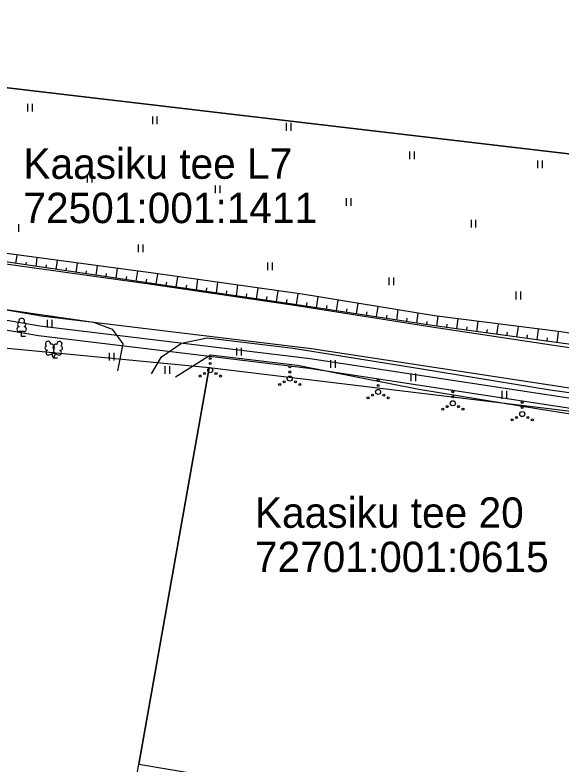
# Model space of a CAD drawing. Extents: x 532656 to 533339, y 6581345 to 6581629.
# Drawn here: x 532876.2 to 532930.1, y 6581458 to 6581531.9 of the extents above; entities that cross this region are included whole.
import ezdxf

# ---------------------------------------------------------------- set-up
doc = ezdxf.new("R2010")
doc.units = 0
for name, color, linetype in [('HALJASTUS', 7, 'Continuous'), ('KASUTUSALA', 7, 'Continuous'), ('PIIR', 7, 'Continuous'), ('PR_SIDE', 7, 'Continuous'), ('PUU', 7, 'Continuous'), ('RELJEEF', 7, 'Continuous'), ('TEE', 7, 'Continuous')]:
    doc.layers.add(name, color=color, linetype=linetype)

msp = doc.modelspace()

# ---------------------------------------------------------------- linework, layer by layer
at = {"layer": 'HALJASTUS'}
for p, q in [((532877.419, 6581523.158), (532877.419, 6581522.397)), ((532877.874, 6581523.158), (532877.874, 6581522.397)), ((532889.752, 6581521.902), (532889.752, 6581521.14)), ((532890.207, 6581521.902), (532890.207, 6581521.14)), ((532902.96, 6581521.263), (532902.96, 6581520.502)), ((532903.415, 6581521.263), (532903.415, 6581520.502)), ((532915.127, 6581518.44), (532915.127, 6581517.679)), ((532915.582, 6581518.44), (532915.582, 6581517.679)), ((532927.787, 6581517.553), (532927.787, 6581516.792)), ((532928.242, 6581517.553), (532928.242, 6581516.792)), ((532883.327, 6581516.137), (532883.327, 6581515.376)), ((532883.782, 6581516.137), (532883.782, 6581515.376)), ((532895.955, 6581515.103), (532895.955, 6581514.342)), ((532896.41, 6581515.103), (532896.41, 6581514.342)), ((532908.879, 6581513.846), (532908.879, 6581513.085)), ((532909.334, 6581513.846), (532909.334, 6581513.085)), ((532921.212, 6581511.703), (532921.212, 6581510.942)), ((532921.667, 6581511.703), (532921.667, 6581510.942)), ((532876.545, 6581511.26), (532876.545, 6581510.499)), ((532888.349, 6581509.265), (532888.349, 6581508.504)), ((532888.804, 6581509.265), (532888.804, 6581508.504)), ((532901.125, 6581507.491), (532901.125, 6581506.73)), ((532901.58, 6581507.491), (532901.58, 6581506.73)), ((532913.088, 6581506.013), (532913.088, 6581505.252)), ((532913.543, 6581506.013), (532913.543, 6581505.252)), ((532925.643, 6581504.609), (532925.643, 6581503.848)), ((532926.098, 6581504.609), (532926.098, 6581503.848)), ((532879.354, 6581501.818), (532879.354, 6581501.057)), ((532879.809, 6581501.818), (532879.809, 6581501.057)), ((532898.063, 6581499.063), (532898.063, 6581498.302)), ((532898.518, 6581499.063), (532898.518, 6581498.302)), ((532885.49, 6581498.566), (532885.49, 6581497.805)), ((532885.945, 6581498.566), (532885.945, 6581497.805)), ((532890.989, 6581497.249), (532890.989, 6581496.488)), ((532891.444, 6581497.249), (532891.444, 6581496.488)), ((532907.347, 6581497.838), (532907.347, 6581497.077)), ((532907.802, 6581497.838), (532907.802, 6581497.077)), ((532915.281, 6581496.529), (532915.281, 6581495.768)), ((532915.736, 6581496.529), (532915.736, 6581495.768)), ((532924.269, 6581494.798), (532924.269, 6581494.037)), ((532924.724, 6581494.798), (532924.724, 6581494.037))]:
    msp.add_line(p, q, dxfattribs=at)
msp.add_lwpolyline([(532892.02, 6581496.19), (532895.502, 6581498.379), (532904.073, 6581497.349), (532916.051, 6581494.964), (532928.105, 6581493.009), (532933.125, 6581492.214), (532933.659, 6581491.084)], dxfattribs=at)
for centre, radius in [((532895.468, 6581498.001), 0.1), ((532895.468, 6581497.501), 0.1), ((532903.319, 6581497.174), 0.1), ((532894.903, 6581496.526), 0.1), ((532895.468, 6581496.851), 0.25), ((532896.033, 6581496.526), 0.1), ((532903.319, 6581496.674), 0.1), ((532894.468, 6581496.276), 0.1), ((532896.468, 6581496.276), 0.1), ((532902.754, 6581495.699), 0.1), ((532903.319, 6581496.024), 0.25), ((532903.884, 6581495.699), 0.1), ((532912.039, 6581495.851), 0.1), ((532902.319, 6581495.449), 0.1), ((532904.319, 6581495.449), 0.1), ((532912.039, 6581495.351), 0.1), ((532911.474, 6581494.376), 0.1), ((532912.039, 6581494.701), 0.25), ((532912.604, 6581494.376), 0.1), ((532919.417, 6581494.729), 0.1), ((532919.417, 6581494.229), 0.1), ((532911.039, 6581494.126), 0.1), ((532913.039, 6581494.126), 0.1), ((532919.417, 6581493.579), 0.25), ((532926.265, 6581493.665), 0.1), ((532918.417, 6581493.004), 0.1), ((532918.852, 6581493.254), 0.1), ((532919.982, 6581493.254), 0.1), ((532920.417, 6581493.004), 0.1), ((532926.265, 6581493.165), 0.1), ((532925.265, 6581491.94), 0.1), ((532925.7, 6581492.19), 0.1), ((532926.265, 6581492.515), 0.25), ((532926.83, 6581492.19), 0.1), ((532927.265, 6581491.94), 0.1)]:
    msp.add_circle(centre, radius, dxfattribs=at)
at = {"layer": 'KASUTUSALA'}
for points in [[(532799.662, 6581479.424), (532838.202, 6581500.971), (532843.839, 6581502.808), (532856.06, 6581504.74), (532864.381, 6581504.708), (532878.783, 6581502.228), (532905.462, 6581499.009), (532934.405, 6581494.582), (532940.328, 6581500.726), (532975.953, 6581496.54), (532984.828, 6581495.375), (532991.779, 6581493.915), (533009.862, 6581492.726), (533014.729, 6581492.033), (533013.98, 6581493.304), (533015.896, 6581507.087)], [(533020.132, 6581489.243), (533009.655, 6581490.735), (532991.507, 6581491.928), (532984.492, 6581493.402), (532975.706, 6581494.555), (532941.079, 6581498.624), (532935.126, 6581492.449), (532905.191, 6581497.027), (532878.493, 6581500.248), (532864.206, 6581502.709), (532856.214, 6581502.739), (532844.308, 6581500.857), (532839.008, 6581499.129), (532800.682, 6581477.703)]]:
    msp.add_lwpolyline(points, dxfattribs=at)
at = {"layer": 'PIIR'}
for points in [[(532997.696, 6581510.35), (532853.02, 6581527.38), (532766.54, 6581476.67), (532710.965, 6581584.147)], [(532997.696, 6581484.842), (532936.25, 6581492.16), (532895.36, 6581497.07), (532858.61, 6581500.62), (532765.26, 6581446.64), (532740.99, 6581450.83), (532726.7, 6581453.3), (532853.02, 6581527.38), (532997.696, 6581510.35)]]:
    msp.add_lwpolyline(points, dxfattribs=at)
for points in [[(532858.61, 6581500.62), (532765.26, 6581446.64), (532882.56, 6581425.55), (532888.42, 6581457.95), (532895.36, 6581497.07)], [(532895.36, 6581497.07), (532888.42, 6581457.95), (532930.2, 6581450.9), (532936.25, 6581492.16)]]:
    msp.add_lwpolyline(points, close=True, dxfattribs=at)
at = {"layer": 'PR_SIDE'}
msp.add_lwpolyline([(532685.797, 6581460.812), (532752.673, 6581449.895), (532752.642, 6581449.863), (532756.241, 6581452.319), (532771.22, 6581460.368), (532800.172, 6581478.564), (532838.605, 6581500.05), (532844.074, 6581501.833), (532856.137, 6581503.74), (532864.294, 6581503.709), (532878.638, 6581501.239), (532905.327, 6581498.018), (532934.766, 6581493.516), (532940.704, 6581499.675), (532975.83, 6581495.548), (532984.66, 6581494.389), (532991.644, 6581492.922), (533009.759, 6581491.731), (533020.322, 6581490.227)], dxfattribs=at)
at = {"layer": 'PUU'}
for p, q in [((532877.086, 6581500.66), (532876.606, 6581500.66)), ((532876.845, 6581500.185), (532876.845, 6581500.66)), ((532877.226, 6581500.185), (532876.845, 6581500.185)), ((532879.562, 6581498.372), (532880.007, 6581498.547)), ((532880.002, 6581498.037), (532879.827, 6581498.477)), ((532880.002, 6581498.037), (532880.182, 6581498.477)), ((532880.382, 6581498.037), (532880.002, 6581498.037)), ((532880.007, 6581498.547), (532880.447, 6581498.367))]:
    msp.add_line(p, q, dxfattribs=at)
msp.add_lwpolyline([(532880.007, 6581499.042), (532879.987, 6581498.967), (532879.987, 6581498.947), (532879.997, 6581498.917), (532880.017, 6581498.882), (532880.022, 6581498.862), (532880.007, 6581498.827), (532879.982, 6581498.777), (532879.977, 6581498.752), (532879.982, 6581498.737), (532879.992, 6581498.707), (532880.027, 6581498.647), (532880.032, 6581498.627), (532880.027, 6581498.607), (532880.012, 6581498.572), (532880.007, 6581498.547)], dxfattribs=at)
for centre, radius, start, end in [((532876.845, 6581501.705), 0.277, 332.5799, 207.4201), ((532876.608, 6581500.898), 0.238, 90.0016, 269.3953), ((532876.675, 6581501.358), 0.233, 109.02174, 253.14154), ((532877.016, 6581501.358), 0.233, 286.85082, 70.98591), ((532877.083, 6581500.898), 0.238, 270.6047, 89.9984), ((532879.445, 6581499.451), 0.256, 111.50269, 232.51731), ((532879.445, 6581499.451), 0.256, 350.48556, 111.50017), ((532880.581, 6581499.442), 0.256, 67.6168, 188.63142), ((532880.581, 6581499.442), 0.256, 306.59966, 67.61428), ((532879.371, 6581499.039), 0.224, 111.43041, 274.49868), ((532879.476, 6581498.595), 0.237, 111.50143, 291.50036), ((532879.78, 6581499.2), 0.224, 308.50412, 111.57247), ((532880.006, 6581498.804), 0.237, 66.76552, 111.50149), ((532880.243, 6581499.196), 0.225, 67.7016, 230.51262), ((532880.537, 6581498.587), 0.237, 247.61661, 67.61554), ((532880.648, 6581499.029), 0.224, 264.6183, 67.68657)]:
    msp.add_arc(centre, radius, start, end, dxfattribs=at)
at = {"layer": 'RELJEEF'}
for p, q in [((532876.284, 6581507.389), (532876.406, 6581508.222)), ((532878.262, 6581507.097), (532878.389, 6581507.956)), ((532880.241, 6581506.806), (532880.371, 6581507.691)), ((532877.273, 6581507.243), (532877.314, 6581507.525)), ((532879.252, 6581506.951), (532879.294, 6581507.242)), ((532881.23, 6581506.66), (532881.274, 6581506.959)), ((532882.22, 6581506.514), (532882.354, 6581507.425)), ((532884.198, 6581506.223), (532884.336, 6581507.16)), ((532886.177, 6581505.931), (532886.319, 6581506.894)), ((532883.209, 6581506.369), (532883.254, 6581506.677)), ((532885.188, 6581506.077), (532885.234, 6581506.394)), ((532887.166, 6581505.786), (532887.214, 6581506.111)), ((532888.155, 6581505.64), (532888.301, 6581506.629)), ((532890.134, 6581505.349), (532890.282, 6581506.36)), ((532889.145, 6581505.494), (532889.194, 6581505.828)), ((532891.124, 6581505.205), (532891.173, 6581505.544)), ((532892.113, 6581505.06), (532892.262, 6581506.081)), ((532894.092, 6581504.771), (532894.243, 6581505.802)), ((532896.071, 6581504.482), (532896.223, 6581505.523)), ((532893.103, 6581504.916), (532893.153, 6581505.258)), ((532895.082, 6581504.627), (532895.132, 6581504.972)), ((532897.061, 6581504.337), (532897.112, 6581504.686)), ((532898.05, 6581504.193), (532898.204, 6581505.244)), ((532900.029, 6581503.904), (532900.184, 6581504.965)), ((532902.008, 6581503.615), (532902.165, 6581504.686)), ((532899.04, 6581504.048), (532899.091, 6581504.4)), ((532901.019, 6581503.759), (532901.071, 6581504.115)), ((532903.987, 6581503.325), (532904.145, 6581504.407)), ((532905.964, 6581503.023), (532906.129, 6581504.093)), ((532902.998, 6581503.47), (532903.05, 6581503.829)), ((532904.976, 6581503.175), (532905.031, 6581503.535)), ((532906.952, 6581502.87), (532907.007, 6581503.224)), ((532907.941, 6581502.718), (532908.103, 6581503.771)), ((532909.917, 6581502.413), (532910.077, 6581503.448)), ((532908.929, 6581502.565), (532908.983, 6581502.913)), ((532910.906, 6581502.26), (532910.958, 6581502.603)), ((532911.894, 6581502.108), (532912.051, 6581503.126)), ((532913.871, 6581501.803), (532914.025, 6581502.804)), ((532915.847, 6581501.498), (532915.999, 6581502.482)), ((532912.882, 6581501.956), (532912.934, 6581502.292)), ((532914.859, 6581501.651), (532914.91, 6581501.981)), ((532916.836, 6581501.346), (532916.886, 6581501.671)), ((532917.825, 6581501.201), (532917.959, 6581502.175)), ((532919.806, 6581500.928), (532919.943, 6581501.921)), ((532921.788, 6581500.656), (532921.927, 6581501.668)), ((532918.816, 6581501.065), (532918.861, 6581501.392)), ((532920.797, 6581500.792), (532920.843, 6581501.126)), ((532923.769, 6581500.384), (532923.911, 6581501.415)), ((532925.75, 6581500.111), (532925.895, 6581501.162)), ((532922.778, 6581500.52), (532922.825, 6581500.86)), ((532924.76, 6581500.247), (532924.807, 6581500.594)), ((532926.741, 6581499.975), (532926.79, 6581500.328)), ((532927.732, 6581499.839), (532927.879, 6581500.909)), ((532929.713, 6581499.566), (532929.863, 6581500.656)), ((532928.722, 6581499.702), (532928.772, 6581500.062))]:
    msp.add_line(p, q, dxfattribs=at)
for points in [[(532990.32, 6581511.282), (532991.842, 6581500.091), (532992.434, 6581496.294), (532992.243, 6581494.55), (532987.443, 6581493.612), (532974.703, 6581494.609), (532961.03, 6581496.282), (532943.56, 6581498.546), (532930.091, 6581500.627), (532917.608, 6581502.219), (532904.555, 6581504.35), (532889.827, 6581506.424), (532874.089, 6581508.532), (532860.585, 6581510.222), (532852.458, 6581510.268)], [(532991.295, 6581511.036), (532993.491, 6581500.256), (532994.205, 6581496.453), (532994.102, 6581494.569), (532992.018, 6581493.179), (532987.251, 6581492.777), (532974.607, 6581493.731), (532960.859, 6581495.351), (532943.377, 6581497.668), (532929.887, 6581499.542), (532917.361, 6581501.265), (532904.238, 6581503.289), (532889.482, 6581505.445), (532873.903, 6581507.739), (532860.397, 6581509.287), (532852.458, 6581510.268)]]:
    msp.add_lwpolyline(points, dxfattribs=at)
at = {"layer": 'TEE'}
for points in [[(532992.127, 6581511.166), (532994.877, 6581500.414), (532995.992, 6581497.284), (532996.535, 6581494.967), (532995.038, 6581493.06), (532992.109, 6581492.211), (532987.192, 6581492.522), (532974.603, 6581493.571), (532960.836, 6581495.043), (532943.355, 6581497.307), (532929.83, 6581499.24), (532917.328, 6581501.087), (532904.202, 6581503.175), (532889.432, 6581505.339), (532873.836, 6581507.526), (532860.39, 6581509.056), (532853.923, 6581509.639), (532847.694, 6581509.868), (532843.333, 6581510.842), (532837.551, 6581513.019), (532831.36, 6581515.277)], [(532767.433, 6581459.775), (532769.763, 6581460.862), (532776.446, 6581464.64), (532786.616, 6581471.204), (532796.99, 6581477.695), (532807.38, 6581484.085), (532818.009, 6581490.276), (532828.082, 6581495.934), (532837.804, 6581500.488), (532846.951, 6581503.331), (532856.666, 6581504.417), (532863.379, 6581504.434), (532873.451, 6581503.101), (532883.953, 6581501.601), (532885.768, 6581500.904), (532886.826, 6581499.461), (532886.304, 6581496.797)], [(532889.672, 6581496.482), (532890.651, 6581498.163), (532892.641, 6581499.514), (532895.155, 6581500.05), (532903.662, 6581499.012), (532916.349, 6581496.974), (532929.017, 6581494.897), (532935.648, 6581493.994), (532936.42, 6581492.855), (532936.468, 6581491.225)]]:
    msp.add_lwpolyline(points, dxfattribs=at)

# ---------------------------------------------------------------- texts
at = {"layer": 'PIIR'}
for s, p in [('Kaasiku tee L7', (532877.018, 6581515.751)), ('72501:001:1411', (532877.018, 6581511.376)), ('Kaasiku tee 20', (532899.877, 6581481.288)), ('72701:001:0615', (532899.877, 6581476.913))]:
    msp.add_text(s, height=3, dxfattribs=at).set_placement(p)

doc.saveas('drawing.dxf')
